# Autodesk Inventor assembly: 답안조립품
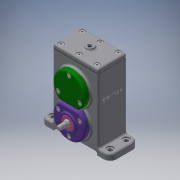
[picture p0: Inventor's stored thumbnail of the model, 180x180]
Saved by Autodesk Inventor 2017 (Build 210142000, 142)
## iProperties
Part Number: 답안조립품
Material: 일반
Document SubType Name: Assembly
Designer: mrc
Mass: 1460.94 g
Surface Area: 1575.48 cm^2
Volume: 385.029 cm^3
Density: 3.79435 g/cm^3
Author: mrc
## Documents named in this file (24)
- C:\Users\mrc\Desktop\600506V1015\답안조립품.iam
- C:\Users\mrc\Desktop\600506V1015\본체.ipt
- C:\Users\mrc\Desktop\600506V1015\개스킷 A.ipt
- C:\Users\mrc\Desktop\600506V1015\개스킷 B.ipt
- C:\Users\mrc\Desktop\600506V1015\개스킷 C.ipt
- C:\Users\mrc\Desktop\600506V1015\베어링 6001.ipt
- 베어링 6001.ipt
- C:\Users\mrc\Desktop\600506V1015\베어링 6002.ipt
- 베어링 6002.ipt
- C:\Users\mrc\Desktop\600506V1015\볼트 M4.ipt
- C:\Users\mrc\Desktop\600506V1015\스퍼기어 A.ipt
- C:\Users\mrc\Desktop\600506V1015\스퍼기어 B.ipt
- C:\Users\mrc\Desktop\600506V1015\오일 실 10 20 7.ipt
- C:\Users\mrc\Desktop\600506V1015\오일 실 12 22 7.ipt
- C:\Users\mrc\Desktop\600506V1015\축 A.ipt
- C:\Users\mrc\Desktop\600506V1015\축 B.ipt
- C:\Users\mrc\Desktop\600506V1015\칼라.ipt
- C:\Users\mrc\Desktop\600506V1015\커버 A.ipt
- C:\Users\mrc\Desktop\600506V1015\커버 B.ipt
- C:\Users\mrc\Desktop\600506V1015\커버 C.ipt
- C:\Users\mrc\Desktop\600506V1015\커버 D.ipt
- C:\Users\mrc\Desktop\600506V1015\커버 E.ipt
- C:\Users\mrc\Desktop\600506V1015\키 4 x 4 x 12.ipt
- C:\Users\mrc\Desktop\600506V1015\키 5 x 5 x 12.ipt
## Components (5 placed, 3 different names)
1. 개스킷 A:1
2. 개스킷 B:1
3. 개스킷 C:1
4. 개스킷 B:2
5. 개스킷 B:3
